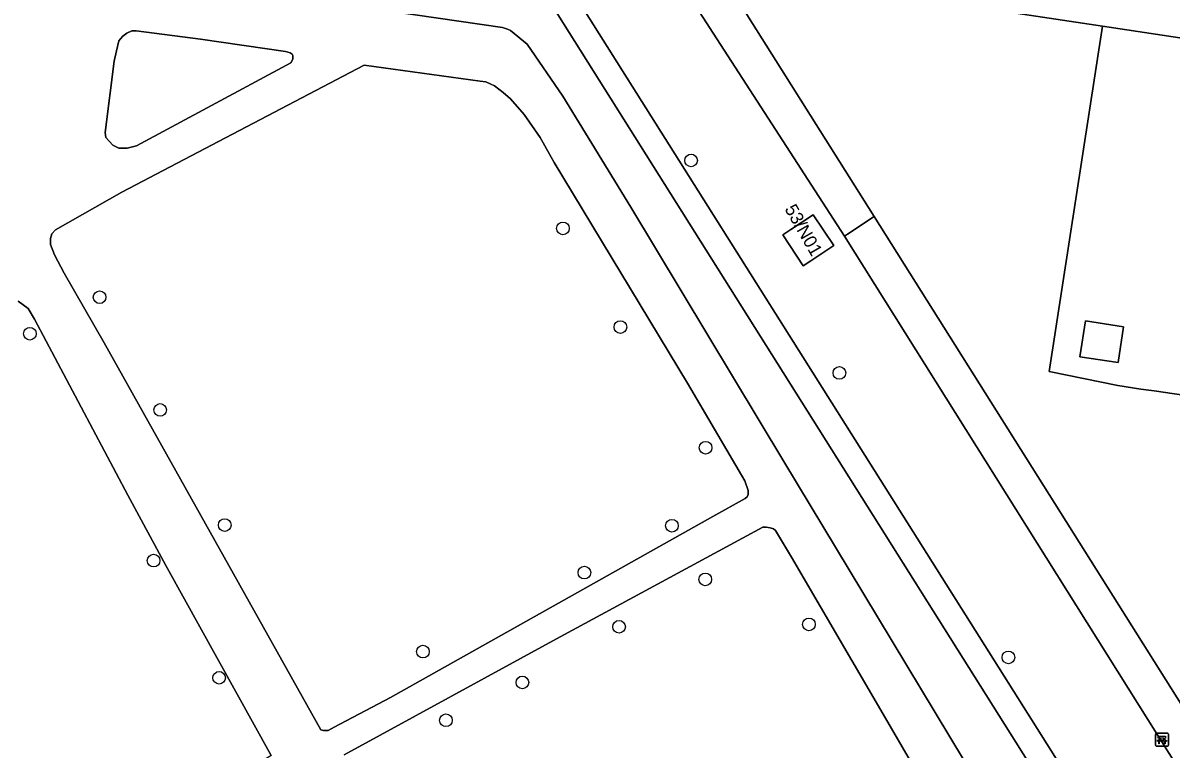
# Model space of a CAD drawing. Extents: x 163008 to 163854, y 382777 to 383982.
# Drawn here: x 163408.4 to 163497.1, y 383156.9 to 383213.1 of the extents above; entities that cross this region are included whole.
import ezdxf

# ---------------------------------------------------------------- set-up
doc = ezdxf.new("R2010")
doc.units = 0
for name, color, linetype in [('IMGEO_Bank', 7, 'Continuous'), ('IMGEO_Boom', 7, 'Continuous'), ('IMGEO_Erf', 7, 'Continuous'), ('IMGEO_Groenvoorziening', 7, 'Continuous'), ('IMGEO_Hek', 7, 'Continuous'), ('IMGEO_Pand', 7, 'Continuous'), ('IMGEO_Pand_nummerreeks', 7, 'Continuous'), ('IMGEO_Voetpad_gesloten', 7, 'Continuous'), ('IMGEO_Voetpad_open', 7, 'Continuous')]:
    doc.layers.add(name, color=color, linetype=linetype)

msp = doc.modelspace()

# ---------------------------------------------------------------- linework, layer by layer
at = {"layer": 'IMGEO_Bank'}
for p, q in [((163495.939, 383157.246), (163495.939, 383158.087)), ((163495.939, 383158.087), (163495.939, 383157.246)), ((163496.014, 383158.171), (163496.855, 383158.171)), ((163496.855, 383158.171), (163496.014, 383158.171)), ((163496.636, 383157.569), (163496.243, 383157.569)), ((163496.248, 383157.677), (163496.248, 383157.783)), ((163496.292, 383157.783), (163496.292, 383157.677)), ((163496.58, 383157.789), (163496.298, 383157.789)), ((163496.298, 383157.671), (163496.58, 383157.671)), ((163496.586, 383157.677), (163496.586, 383157.783)), ((163496.63, 383157.783), (163496.63, 383157.677)), ((163496.939, 383158.096), (163496.939, 383157.255)), ((163496.939, 383157.255), (163496.939, 383158.096)), ((163496.864, 383157.171), (163496.023, 383157.171)), ((163496.023, 383157.171), (163496.864, 383157.171))]:
    msp.add_line(p, q, dxfattribs=at)
for points in [[(163496.186, 383157.569), (163496.044, 383157.569), (163496.156, 383157.671), (163496.242, 383157.671)], [(163496.242, 383157.789), (163496.156, 383157.789), (163496.156, 383157.95), (163496.719, 383157.95), (163496.719, 383157.789), (163496.636, 383157.789)], [(163496.236, 383157.562), (163496.236, 383157.355), (163496.193, 383157.355), (163496.193, 383157.562)], [(163496.636, 383157.671), (163496.719, 383157.671), (163496.831, 383157.569), (163496.692, 383157.569)], [(163496.686, 383157.562), (163496.686, 383157.355), (163496.642, 383157.355), (163496.642, 383157.562)]]:
    msp.add_lwpolyline(points, dxfattribs=at)
for centre, radius, start, end in [((163496.017, 383158.093), 0.0779, 92.4484, 184.28452), ((163496.017, 383158.093), 0.0779, 92.4484, 184.28452), ((163496.186, 383157.562), 0.00671, 2.89567, 87.10433), ((163496.243, 383157.562), 0.00671, 92.89567, 177.10433), ((163496.241, 383157.782), 0.00671, 2.89567, 87.10433), ((163496.241, 383157.678), 0.00671, 272.89567, 357.10433), ((163496.298, 383157.782), 0.00671, 92.89567, 177.10433), ((163496.298, 383157.678), 0.00671, 182.89567, 267.10433), ((163496.58, 383157.782), 0.00671, 2.89567, 87.10433), ((163496.58, 383157.678), 0.00671, 272.89567, 357.10433), ((163496.637, 383157.782), 0.00671, 92.89567, 177.10433), ((163496.637, 383157.678), 0.00671, 182.89567, 267.10433), ((163496.635, 383157.562), 0.00671, 2.89567, 87.10433), ((163496.692, 383157.562), 0.00671, 92.89567, 177.10433), ((163496.861, 383158.093), 0.0779, 2.4484, 94.28452), ((163496.861, 383158.093), 0.0779, 2.4484, 94.28452), ((163496.017, 383157.249), 0.0779, 182.4484, 274.28452), ((163496.017, 383157.249), 0.0779, 182.4484, 274.28452), ((163496.861, 383157.249), 0.0779, 272.4484, 4.28452), ((163496.861, 383157.249), 0.0779, 272.4484, 4.28452)]:
    msp.add_arc(centre, radius, start, end, dxfattribs=at)
at = {"layer": 'IMGEO_Boom'}
for centre in [(163460.06, 383202.449), (163450.153, 383197.198), (163414.352, 383191.882), (163408.963, 383189.06), (163454.595, 383189.572), (163471.519, 383186.023), (163419.033, 383183.162), (163461.179, 383180.239), (163424.019, 383174.265), (163458.578, 383174.213), (163418.529, 383171.52), (163451.816, 383170.594), (163461.147, 383170.069), (163454.487, 383166.399), (163469.165, 383166.587), (163439.337, 383164.484), (163484.58, 383164.031), (163423.59, 383162.457), (163447.026, 383162.096), (163441.117, 383159.173)]:
    msp.add_circle(centre, 0.489, dxfattribs=at)
at = {"layer": 'IMGEO_Erf'}
for points in [[(163529.514, 383207.154), (163513.94, 383209.504), (163511.464, 383209.877), (163491.84, 383212.838), (163487.723, 383186.135), (163493.021, 383185.055), (163494.8, 383184.78), (163495.83, 383184.63), (163504.561, 383183.36), (163505.941, 383183.159), (163520.659, 383181.018), (163525.379, 383180.331)], [(163490.091, 383187.278), (163490.521, 383190.052), (163493.472, 383189.595), (163493.043, 383186.821)]]:
    msp.add_lwpolyline(points, close=True, dxfattribs=at)
at = {"layer": 'IMGEO_Groenvoorziening'}
for points in [[(163507.75, 383121.545), (163447.879, 383216.74), (163416.32, 383221.516), (163416.361, 383221.827), (163415.792, 383221.889), (163415.741, 383221.609), (163415.688, 383221.617), (163415.341, 383218.899), (163415.508, 383217.937), (163416.028, 383216.963), (163416.531, 383216.176), (163417.203, 383215.949), (163422.151, 383215.741), (163425.875, 383215.416), (163430.403, 383214.945), (163445.485, 383212.724), (163445.861, 383212.612), (163446.109, 383212.498), (163447.383, 383211.442), (163450.141, 383207.424), (163455.403, 383198.833), (163467.222, 383179.175), (163472.26, 383170.797), (163483.359, 383152.387)], [(163400.933, 383141.327), (163427.609, 383156.446), (163419.463, 383171.138), (163416.527, 383176.567), (163409.326, 383190.186), (163408.845, 383191.015), (163408.064, 383191.57)], [(163485.083, 383142.159), (163474.719, 383159.954), (163467.824, 383171.793), (163466.577, 383173.855), (163466.412, 383173.962), (163466.155, 383174.049), (163465.856, 383174.114), (163465.599, 383174.114), (163449.669, 383165.471), (163433.25, 383156.513)]]:
    msp.add_lwpolyline(points, dxfattribs=at)
for points in [[(163447.879, 383216.74), (163507.75, 383121.545), (163509.255, 383122.906), (163448.47, 383219.382)], [(163471.916, 383196.595), (163458.131, 383217.924), (163448.47, 383219.382), (163509.255, 383122.906), (163514.914, 383128.02)], [(163525.379, 383180.331), (163520.659, 383181.018), (163505.941, 383183.159), (163504.561, 383183.36), (163495.83, 383184.63), (163494.8, 383184.78), (163493.021, 383185.055), (163487.723, 383186.135), (163491.84, 383212.838), (163462.133, 383217.32), (163474.207, 383198.128), (163517.084, 383129.951), (163518.36, 383131.075)], [(163414.773, 383204.611), (163414.843, 383204.232), (163415.386, 383203.645), (163415.831, 383203.414), (163416.489, 383203.414), (163417.201, 383203.591), (163429.14, 383209.992), (163429.296, 383210.285), (163429.296, 383210.559), (163429.237, 383210.677), (163429.074, 383210.764), (163428.73, 383210.875), (163422.151, 383211.832), (163417.187, 383212.468), (163416.849, 383212.468), (163416.458, 383212.292), (163416.144, 383212.067), (163415.957, 383211.853), (163415.85, 383211.687), (163415.661, 383210.935), (163415.484, 383210.138)], [(163410.567, 383195.966), (163410.873, 383195.161), (163411.617, 383193.73), (163414.702, 383188.359), (163431.451, 383158.437), (163431.648, 383158.376), (163432.016, 383158.376), (163432.475, 383158.647), (163436.843, 383160.924), (163461.736, 383174.925), (163464.237, 383176.329), (163464.383, 383176.44), (163464.47, 383176.622), (163464.47, 383176.942), (163464.202, 383177.685), (163459.781, 383185.239), (163449.488, 383202.291), (163448.402, 383204.232), (163447.17, 383206.003), (163446.103, 383207.213), (163445.541, 383207.701), (163444.863, 383208.211), (163444.204, 383208.521), (163443.752, 383208.583), (163434.794, 383209.813), (163416.068, 383200.002), (163410.951, 383197.093), (163410.655, 383196.77), (163410.567, 383196.427)], [(163469.303, 383194.691), (163468.727, 383194.307), (163467.138, 383196.69), (163467.774, 383197.114), (163469.489, 383198.257), (163471.077, 383195.874)]]:
    msp.add_lwpolyline(points, close=True, dxfattribs=at)
at = {"layer": 'IMGEO_Hek'}
for points in [[(163507.75, 383121.545), (163447.879, 383216.74)], [(163495.83, 383184.63), (163494.8, 383184.78), (163493.021, 383185.055), (163487.723, 383186.135), (163491.84, 383212.838)], [(163504.561, 383183.36), (163495.83, 383184.63)]]:
    msp.add_lwpolyline(points, dxfattribs=at)
at = {"layer": 'IMGEO_Pand'}
for points in [[(163469.303, 383194.691), (163471.077, 383195.874), (163469.489, 383198.257), (163467.774, 383197.114), (163467.138, 383196.69), (163468.727, 383194.307)], [(163490.091, 383187.278), (163493.043, 383186.821), (163493.472, 383189.595), (163490.521, 383190.052)]]:
    msp.add_lwpolyline(points, close=True, dxfattribs=at)
at = {"layer": 'IMGEO_Voetpad_gesloten'}
for points in [[(163483.359, 383152.387), (163472.26, 383170.797), (163467.222, 383179.175), (163455.403, 383198.833), (163450.141, 383207.424), (163447.383, 383211.442), (163446.109, 383212.498), (163445.861, 383212.612), (163445.485, 383212.724), (163430.403, 383214.945)], [(163408.064, 383191.57), (163408.845, 383191.015), (163409.326, 383190.186), (163416.527, 383176.567), (163419.463, 383171.138), (163427.609, 383156.446), (163400.933, 383141.327)], [(163433.25, 383156.513), (163449.669, 383165.471), (163465.599, 383174.114), (163465.856, 383174.114), (163466.155, 383174.049), (163466.412, 383173.962), (163466.577, 383173.855), (163467.824, 383171.793), (163474.719, 383159.954), (163485.083, 383142.159)]]:
    msp.add_lwpolyline(points, dxfattribs=at)
for points in [[(163414.773, 383204.611), (163415.484, 383210.138), (163415.661, 383210.935), (163415.85, 383211.687), (163415.957, 383211.853), (163416.144, 383212.067), (163416.458, 383212.292), (163416.849, 383212.468), (163417.187, 383212.468), (163422.151, 383211.832), (163428.73, 383210.875), (163429.074, 383210.764), (163429.237, 383210.677), (163429.296, 383210.559), (163429.296, 383210.285), (163429.14, 383209.992), (163417.201, 383203.591), (163416.489, 383203.414), (163415.831, 383203.414), (163415.386, 383203.645), (163414.843, 383204.232)], [(163410.567, 383195.966), (163410.567, 383196.427), (163410.655, 383196.77), (163410.951, 383197.093), (163416.068, 383200.002), (163434.794, 383209.813), (163443.752, 383208.583), (163444.204, 383208.521), (163444.863, 383208.211), (163445.541, 383207.701), (163446.103, 383207.213), (163447.17, 383206.003), (163448.402, 383204.232), (163449.488, 383202.291), (163459.781, 383185.239), (163464.202, 383177.685), (163464.47, 383176.942), (163464.47, 383176.622), (163464.383, 383176.44), (163464.237, 383176.329), (163461.736, 383174.925), (163436.843, 383160.924), (163432.475, 383158.647), (163432.016, 383158.376), (163431.648, 383158.376), (163431.451, 383158.437), (163414.702, 383188.359), (163411.617, 383193.73), (163410.873, 383195.161)], [(163474.207, 383198.128), (163472.144, 383196.747), (163471.916, 383196.595), (163514.914, 383128.02), (163517.084, 383129.951)]]:
    msp.add_lwpolyline(points, close=True, dxfattribs=at)
at = {"layer": 'IMGEO_Voetpad_open'}
msp.add_lwpolyline([(163419.272, 383232.3), (163419.024, 383231.013), (163418.093, 383231.161), (163417.926, 383229.893), (163440.851, 383226.277), (163440.336, 383223.072), (163417.441, 383226.495), (163417.095, 383224.115), (163448.47, 383219.382), (163458.131, 383217.924), (163458.854, 383217.815), (163462.133, 383217.32), (163491.84, 383212.838), (163511.464, 383209.877), (163513.94, 383209.504), (163529.514, 383207.154), (163531.766, 383206.678)], dxfattribs=at)
msp.add_lwpolyline([(163462.133, 383217.32), (163458.854, 383217.815), (163458.131, 383217.924), (163471.916, 383196.595), (163472.144, 383196.747), (163474.207, 383198.128)], close=True, dxfattribs=at)

# ---------------------------------------------------------------- texts
at = {"layer": 'IMGEO_Pand_nummerreeks'}
msp.add_text('53/N01', height=1, rotation=299.74488, dxfattribs=at).set_placement((163467.252, 383198.708))

doc.saveas('drawing.dxf')
